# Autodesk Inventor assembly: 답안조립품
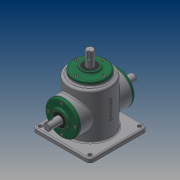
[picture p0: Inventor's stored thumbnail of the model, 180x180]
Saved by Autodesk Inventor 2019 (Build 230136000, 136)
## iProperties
Created: 2019-03
Part Number: 답안조립품
Material: 일반
Document SubType Name: Assembly
Designer: PC312-03
Author: PC312-03
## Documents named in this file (16)
- C:\Users\PC312-03\Desktop\490314V1011\답안조립품.iam
- C:\Users\PC312-03\Desktop\490314V1011\본체.ipt
- C:\Users\PC312-03\Desktop\490314V1011\커버.ipt
- C:\Users\PC312-03\Desktop\490314V1011\볼트 M4.ipt
- 볼트 M4.ipt
- C:\Users\PC312-03\Desktop\490314V1011\오일 실.ipt
- 오일 실.ipt
- C:\Users\PC312-03\Desktop\490314V1011\베어링 6203.ipt
- C:\Users\PC312-03\Desktop\490314V1011\메인 축.ipt
- 메인 축.ipt
- C:\Users\PC312-03\Desktop\490314V1011\서브 축.ipt
- 서브 축.ipt
- C:\Users\PC312-03\Desktop\490314V1011\키 5x5.ipt
- C:\Users\PC312-03\Desktop\490314V1011\키 4x4.ipt
- C:\Users\PC312-03\Desktop\490314V1011\메인 베벨기어.ipt
- C:\Users\PC312-03\Desktop\490314V1011\서브 베벨기어.ipt
